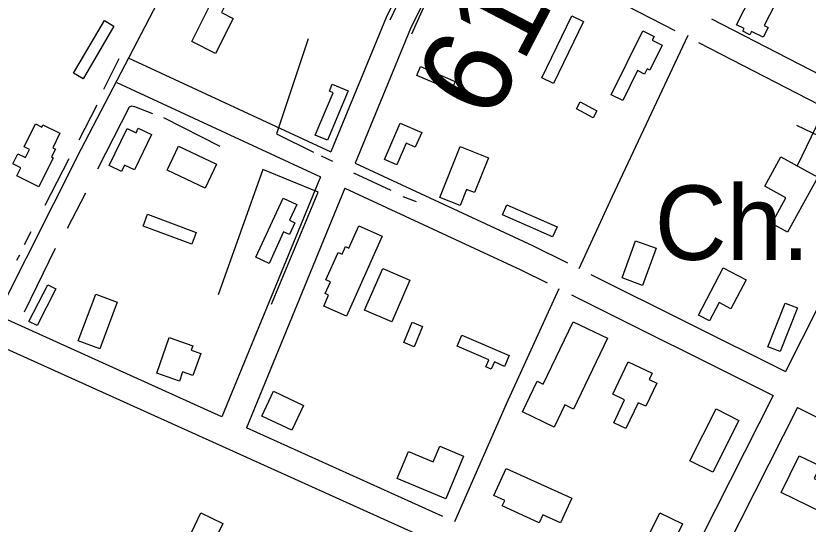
# Model space of a CAD drawing. Extents: x 3361039 to 3398939, y 576572 to 602007.
# Drawn here: x 3386256 to 3387139, y 584104 to 584671 of the extents above; entities that cross this region are included whole.
import ezdxf

# ---------------------------------------------------------------- set-up
doc = ezdxf.new("R2010")
doc.units = 0
for name, color, linetype in [('V-BLDG-IDEN', 7, 'Continuous'), ('V-BLDG-OTLN', 7, 'Continuous'), ('V-ROAD-CNTR', 7, 'Continuous'), ('V-SITE-OTLN', 7, 'Continuous'), ('V-SITE-OTLN-IDEN', 7, 'Continuous'), ('V-SURV-IDEN', 7, 'Continuous'), ('V-TOPO-SHOR', 7, 'Continuous')]:
    doc.layers.add(name, color=color, linetype=linetype)

msp = doc.modelspace()

# ---------------------------------------------------------------- linework, layer by layer
at = {"layer": 'V-BLDG-OTLN'}
for points in [[(3387084.85, 584705.89), (3387107.7, 584694.28), (3387090.35, 584660.15), (3387094.6, 584657.99), (3387089.02, 584647), (3387076.12, 584653.55), (3387074.17, 584649.72), (3387066.41, 584653.66), (3387067.98, 584656.74), (3387059.49, 584661.05), (3387076.68, 584694.89), (3387072.01, 584697.26), (3387076.63, 584706.35), (3387083.35, 584702.94)], [(3386452.24, 584642.31), (3386474.62, 584686.77), (3386488.17, 584679.95), (3386485.44, 584674.52), (3386498.45, 584667.98), (3386478.8, 584628.95)], [(3386842.4, 584601.78), (3386875.98, 584670.75), (3386888.96, 584664.43), (3386855.37, 584595.46)], [(3386320.54, 584607.02), (3386354.84, 584665.63), (3386365.47, 584659.41), (3386331.16, 584600.8)], [(3386919.65, 584582.79), (3386955.02, 584654.14), (3386967.49, 584647.96), (3386965.45, 584643.84), (3386976.7, 584638.26), (3386962.85, 584610.32), (3386959.86, 584611.8), (3386956.98, 584605.99), (3386949.23, 584609.83), (3386932.63, 584576.35)], [(3386707.23, 584614.31), (3386745.96, 584597.78), (3386741.77, 584587.98), (3386703.05, 584604.51)], [(3386626.49, 584587.4), (3386603.39, 584532.19), (3386589.99, 584537.8), (3386609.8, 584585.14), (3386605.63, 584586.88), (3386608.92, 584594.75)], [(3386885.33, 584574.96), (3386903.83, 584564.91), (3386899.55, 584557.04), (3386881.06, 584567.09)], [(3386297.87, 584512.71), (3386281.82, 584480.39), (3386257.46, 584492.49), (3386261.81, 584501.26), (3386252.81, 584505.73), (3386258.45, 584517.09), (3386266.79, 584512.95), (3386271.23, 584521.89), (3386265.33, 584524.82), (3386278.03, 584550.4), (3386285.06, 584546.91), (3386286.36, 584549.54), (3386305.33, 584540.11), (3386297.25, 584523.82), (3386300.21, 584522.34), (3386295.91, 584513.68)], [(3386407.55, 584538.5), (3386388.54, 584499.18), (3386377.37, 584504.58), (3386373.86, 584497.32), (3386360.26, 584503.9), (3386380.27, 584545.3), (3386390.15, 584540.52), (3386392.66, 584545.7)], [(3386667.1, 584510.87), (3386684.67, 584551.24), (3386708.56, 584540.84), (3386701.39, 584524.36), (3386691.3, 584528.76), (3386680.9, 584504.86)], [(3386437.42, 584525.58), (3386479.83, 584505.51), (3386467.17, 584478.75), (3386424.76, 584498.83)], [(3386728.94, 584468.46), (3386751.44, 584525.12), (3386782.9, 584512.63), (3386767.52, 584473.9), (3386758.57, 584477.45), (3386751.45, 584459.52)], [(3387114.53, 584468.11), (3387091.08, 584480.96), (3387108.94, 584513.56), (3387149.95, 584491.08), (3387116.32, 584429.7), (3387098.76, 584439.34)], [(3386523.68, 584401.63), (3386554.13, 584467.52), (3386569.27, 584460.53), (3386561.18, 584443), (3386567.22, 584440.21), (3386561.08, 584426.92), (3386554.6, 584429.91), (3386538.39, 584394.83)], [(3386803.33, 584460.27), (3386859.35, 584435.5), (3386854.44, 584424.4), (3386798.42, 584449.16)], [(3386402.94, 584449.59), (3386457.14, 584429.4), (3386452.25, 584416.27), (3386398.05, 584436.47)], [(3386664.38, 584425.25), (3386624.59, 584335.87), (3386599.3, 584347.13), (3386604.84, 584359.58), (3386601.1, 584361.25), (3386606.85, 584374.18), (3386601.82, 584376.43), (3386615.46, 584407.08), (3386619.84, 584405.13), (3386623.66, 584413.71), (3386627.47, 584412.02), (3386638.49, 584436.78)], [(3386931.8, 584378.71), (3386946.9, 584420.14), (3386969.75, 584411.82), (3386954.64, 584370.39)], [(3386644.93, 584342.7), (3386665.05, 584389.25), (3386695.39, 584376.14), (3386675.27, 584329.59)], [(3387017.03, 584337.32), (3387044.45, 584390), (3387070.14, 584376.63), (3387053.26, 584344.2), (3387040.03, 584351.09), (3387029.48, 584330.83)], [(3386270.8, 584330.11), (3386291.69, 584371.07), (3386300.83, 584366.4), (3386279.94, 584325.45)], [(3386325.81, 584308.46), (3386345.16, 584360.6), (3386369.19, 584351.68), (3386349.85, 584299.54)], [(3387094.45, 584301.99), (3387113.77, 584350.62), (3387127.49, 584345.17), (3387108.17, 584296.54)], [(3386688.64, 584306.72), (3386697.89, 584329.17), (3386709.42, 584324.42), (3386700.17, 584301.97)], [(3386843.94, 584260.23), (3386877.32, 584329.82), (3386915.61, 584311.45), (3386877.69, 584232.41), (3386868.1, 584237.01), (3386856.27, 584212.35), (3386820.87, 584229.33), (3386837.24, 584263.45)], [(3386413.16, 584272.62), (3386427.21, 584312.2), (3386453.28, 584302.95), (3386451.57, 584298.14), (3386462.28, 584294.34), (3386453.62, 584269.95), (3386442.11, 584274.04), (3386438.42, 584263.66)], [(3386753.26, 584314.93), (3386806.19, 584292.06), (3386800.97, 584279.96), (3386789.5, 584284.92), (3386786, 584276.82), (3386779.93, 584279.45), (3386783.35, 584287.37), (3386747.96, 584302.67)], [(3386921.6, 584248.91), (3386938.52, 584285.14), (3386965.42, 584272.59), (3386962.08, 584265.44), (3386970.55, 584261.49), (3386958.42, 584235.5), (3386949.74, 584239.56), (3386936.23, 584210.63), (3386922.62, 584216.97), (3386934.68, 584242.81)], [(3386543.28, 584252.29), (3386576.84, 584236.43), (3386563.76, 584208.73), (3386530.2, 584224.59)], [(3387007.54, 584174.81), (3387036.67, 584232.65), (3387062.18, 584219.8), (3387033.05, 584161.97)], [(3386735.5, 584132.45), (3386681.32, 584154.92), (3386693.8, 584185.01), (3386721.36, 584173.58), (3386728.62, 584191.07), (3386755.23, 584180.03)], [(3387109.3, 584139.23), (3387129.23, 584180.44), (3387152.68, 584169.1), (3387145.86, 584155), (3387167.19, 584144.68), (3387154.08, 584117.58)], [(3386802.86, 584166.32), (3386875.76, 584132.9), (3386863.24, 584105.6), (3386843.53, 584114.63), (3386839.38, 584105.59), (3386798.33, 584124.41), (3386801.15, 584130.55), (3386789.02, 584136.11)], [(3386446, 584081.98), (3386462.49, 584116.57), (3386486.8, 584104.98), (3386470.31, 584070.4)], [(3386941.34, 584050.74), (3386974.06, 584116.82), (3386999.27, 584104.33), (3386966.55, 584038.25)]]:
    msp.add_lwpolyline(points, close=True, dxfattribs=at)
at = {"layer": 'V-ROAD-CNTR'}
for points in [[(3385719.93, 583315.67), (3386054.99, 583977.88), (3386329.09, 584522.22), (3386660, 585157.52)], [(3386727.18, 584788.03), (3386668.86, 584669.15), (3386607.18, 584519.13)], [(3386754.06, 584774.7), (3386696.23, 584656.83), (3386634.42, 584506.48)], [(3386754.06, 584774.7), (3386854.81, 584724.72), (3386990.75, 584654.71)], [(3387031.43, 584667.51), (3387201.78, 584579.78), (3387254.49, 584552.62)], [(3387005.1, 584649), (3386920.97, 584469.29), (3386883.85, 584388.95)], [(3387016.98, 584641.2), (3387188.04, 584553.11), (3387240.96, 584525.84)], [(3386381.31, 584623.96), (3386607.18, 584519.12)], [(3386368.68, 584596.75), (3386595.76, 584491.35)], [(3387240.96, 584525.85), (3387113.89, 584274.37)], [(3386634.41, 584506.48), (3386832.17, 584414.69), (3386870.93, 584395.39)], [(3386595.76, 584491.35), (3386485.8, 584223.92)], [(3386623, 584478.71), (3386513.15, 584211.56)], [(3386622.99, 584478.71), (3386819.16, 584387.66), (3386848.42, 584373.08)], [(3386897.17, 584382.32), (3387113.89, 584274.37)], [(3386861.32, 584366.66), (3386802.87, 584237.75), (3386745.15, 584106.75)], [(3386875.35, 584359.67), (3387100.36, 584247.59)], [(3386485.8, 584223.92), (3386235.18, 584337.14)], [(3386963.05, 583973.68), (3386884.84, 584010.72), (3386222.83, 584309.8)], [(3387100.37, 584247.59), (3386988.25, 584025.71), (3386976.13, 584000.68)], [(3387127.22, 584234.22), (3387015.14, 584012.4), (3387003.24, 583987.83)], [(3387127.22, 584234.22), (3387312.86, 584141.75), (3387367.79, 584114.25)], [(3386732.08, 584112.65), (3386513.15, 584211.56)]]:
    msp.add_lwpolyline(points, dxfattribs=at)
at = {"layer": 'V-SITE-OTLN'}
for p, q in [((3387127.24, 584503.87), (3387153.37, 584557.88)), ((3387162.66, 584531.16), (3387126.66, 584548.59))]:
    msp.add_line(p, q, dxfattribs=at)
at = {"layer": 'V-TOPO-SHOR'}
for p, q in [((3386697.46, 584650.88), (3386747.22, 584762.4)), ((3386673.29, 584666.51), (3386688.04, 584697.74)), ((3386354.35, 584589.3), (3386371.29, 584623.29)), ((3386326.77, 584532.83), (3386346.65, 584571.81)), ((3386483.8, 584525.08), (3386421.01, 584557.36)), ((3386288.98, 584459.86), (3386315.55, 584511.71)), ((3386596.42, 584514.88), (3386609.29, 584508.96)), ((3386632.51, 584495.99), (3386674.2, 584476.46)), ((3386313.81, 584434.33), (3386334.09, 584473.5)), ((3386687.45, 584469.57), (3386702.25, 584463.83)), ((3386265.76, 584415.9), (3386273.24, 584430.49)), ((3386257.29, 584398.61), (3386260.82, 584404.56)), ((3386265.78, 584340.82), (3386300.46, 584411.88))]:
    msp.add_line(p, q, dxfattribs=at)
for points in [[(3386582.09, 584645.3), (3386546.67, 584539.5), (3386587.96, 584518.82)], [(3386347.67, 584500.39), (3386382.91, 584569.33), (3386385.44, 584570.65), (3386388.52, 584569.85), (3386408.32, 584562.12)], [(3386541.1, 584349.44), (3386593.3, 584474.19), (3386531.41, 584499.51), (3386481.56, 584359.69)]]:
    msp.add_lwpolyline(points, dxfattribs=at)

# ---------------------------------------------------------------- texts
at = {"layer": 'V-BLDG-IDEN'}
msp.add_text('Lowery', height=83, dxfattribs=at).set_placement((3386163.26, 584027.19))
at = {"layer": 'V-SITE-OTLN-IDEN'}
msp.add_text('Ch.', height=83, dxfattribs=at).set_placement((3386968.27, 584398.8))
at = {"layer": 'V-SURV-IDEN'}
msp.add_text('6198+73.0', height=100, rotation=62.49866, dxfattribs=at).set_placement((3386786.5, 584550.84))

doc.saveas('drawing.dxf')
